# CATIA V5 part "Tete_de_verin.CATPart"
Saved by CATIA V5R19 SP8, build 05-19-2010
Part number: Tete
Revision: ANY
Definition: UNKNOWN
Nomenclature: Tete de vérin
Source: Unknown
Bounding box of the stored display mesh (mm): x -6.25 to 6.25, y -6.25 to 6.25, z -14.8 to 31.5
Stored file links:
  D:\Documents\1_Travail\1 - ac-limoges.fr\ac-limoges.fr\Emmanuel Maynard - STI2D_Turgot\2 -2I2D\3_SEQUENCE_Serre_Connectée\Dossier technique_SERRE\Maquettes_CATIA\Vérin_Thermodynamique\Tete_de_verin.CATPart
  D:\Documents\1_Travail\1 - ac-limoges.fr\ac-limoges.fr\Emmanuel Maynard - STI2D_Turgot\2 -2I2D\3_SEQUENCE_Serre_Connectée\Dossier technique_SERRE\Maquettes_CATIA\Vérin_Thermodynamique\Verin thermodynamique.CATProduct
  D:\Documents\1_Travail\1 - ac-limoges.fr\ac-limoges.fr\Emmanuel Maynard - STI2D_Turgot\2 -2I2D\3_SEQUENCE_Serre_Connectée\Dossier technique_SERRE\Maquettes_CATIA\Vérin_Thermodynamique\Tige_de_verin.CATPart
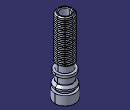
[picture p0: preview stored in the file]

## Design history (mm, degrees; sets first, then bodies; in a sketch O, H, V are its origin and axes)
Body1 "NONE" (main body)
  Solid1: solid without history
